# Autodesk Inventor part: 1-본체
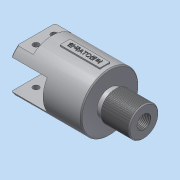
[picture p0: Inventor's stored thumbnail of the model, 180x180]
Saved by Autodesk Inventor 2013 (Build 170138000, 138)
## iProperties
Created: 2019-02
Part Number: 1-본체
Material: 알루미늄 6061
Document SubType Name: Modeling
Designer: Administrator
Density: 2.71 g/cm^3
Mass: 344.897 g
Surface Area: 291.439 cm^2
Volume: 127.268 cm^3
Author: Administrator
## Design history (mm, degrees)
sketch "스케치1"
  geometry: L1 (0, 0)-(72, 0); L2 (0, 14)-(0, 29); L3 (0, 29)-(38, 29); L4 (38, 29)-(38, 13); L5 (38, 13)-(43, 13); L6 (43, 13)-(43, 15); L7 (43, 15)-(72, 15); L8 (72, 15)-(72, 7); L9 (0, 14)-(2.65, 14); L10 (2.65, 14)-(2.65, 17); L11 (2.65, 17)-(7.35, 17); L12 (7.35, 17)-(7.35, 14); L13 (7.35, 14)-(11.65, 14); L14 (11.65, 14)-(11.65, 17); L15 (11.65, 17)-(16.35, 17); L16 (16.35, 17)-(16.35, 14); L17 (16.35, 14)-(20, 14); L18 (20, 14)-(20, 16); L19 (20, 16)-(27, 16); L20 (27, 16)-(27, 4); L21 (27, 4)-(47, 4); L22 (50, 7)-(72, 7); L23 (50, 7)-(47, 4); 2 further points
  constraints: 46 end point, 10 parallel, 7 perpendicular, 4 collinear, 2 horizontal, 2 midpoint, 1 vertical, 1 vertical alignment
  dimensions: "d0" = 58 diameter of L3 L1; "d1" = 38 distance of L2.end L3.end; "d2" = 5 distance of L4.end L5.end; "d3" = 29 distance of L6.end L7.end; "d4" = 26 diameter of L5 L1; "d5" = 30 diameter of L7 L1; "d6" = 7 distance of L18.end L19.end; "d7" = 9 distance of point (5, 17) point (14, 17); "d8" = 5 distance from line of L2 point (5, 17); "d9" = 4.7 distance between parallel lines of L12 L10; "d10" = 4.7 distance between parallel lines of L16 L14; "d11" = 34 diameter of point (5, 17) L1; "d12" = 28 diameter of L13 L1; "d13" = 32 diameter of L19 L1; "d14" = 27 distance between parallel lines of L2 L20; "d15" = 8 diameter of L21 L1; "d16" = 22 distance of L8.end L22.start; "d17" = 14 diameter of L22 L1; "d18" = 28 diameter of L9 L1; "d61" = 45 deg angle of L21 L23
revolve "회전1" sketch "스케치1" stored, may be unused: angle "d19" = 90 deg
feature "스레드1" dims "d20" = 18, "d21" = 0
feature "스레드2" dims "d22" = 10, "d23" = 0
sketch "스케치2"
  geometry: C1 r 29 at (0, 0) reference
extrude "돌출1" join sketch "스케치2" distance "d24" = 36; taper "d25" = 0 deg
sketch "스케치3"
  geometry: L1 (-15, 36.407)-(15, 36.407); L2 (15, 36.407)-(15, -36.407); L3 (15, -36.407)-(-15, -36.407); L4 (-15, -36.407)-(-15, 36.407); C1 r 29 at (0, 0) reference; 2 further points
  constraints: 8 end point, 2 midpoint, 2 parallel, 1 horizontal, 1 horizontal alignment, 1 perpendicular, 1 vertical alignment
  dimensions: "d26" = 30 distance of L1.start L1.end; "d27" = 72.81341 distance of L1.end L2.end
extrude "돌출2" cut sketch "스케치3" distance "d28" = 36; taper "d29" = 0 deg
sketch "스케치4"
  geometry: L1 (22, 43.311)-(53.385, 43.311); L2 (53.385, 43.311)-(53.385, -43.311); L3 (53.385, -43.311)-(22, -43.311); L4 (22, -43.311)-(22, 43.311); 2 further points
  constraints: 8 end point, 2 parallel, 1 horizontal, 1 horizontal alignment, 1 midpoint, 1 perpendicular
  dimensions: "d30" = 22 distance of point (22, 0) point (0, 0); "d31" = 31.38509 distance of L1.start L1.end; "d32" = 86.62286 distance of L1.end L2.end
extrude "돌출3" cut sketch "스케치4" distance "d33" = 16; taper "d34" = 0 deg
sketch "스케치5"
  geometry: L1 (16, 0)-(16, -37.789) reference; L2 (16, 5.925)-(16, -43.714) reference; C1 r 3 at (7, -9.894); C2 r 3 at (7, -27.894); 2 further points
  constraints: 2 centre point, 1 equal radius, 1 midpoint, 1 vertical alignment
  dimensions: "d35" = 9 distance from line of L1 C1.centre; "d36" = 18 distance of C1.centre C2.centre; "d37" = 9 horizontal distance of point (16, -18.894) C2.centre; "d38" = 6 diameter of C2
extrude "돌출4" cut sketch "스케치5" stored distance "d39" = 16; taper "d40" = 0 deg
node "작업 평면1"
sketch "스케치6"
  geometry: L1 (-7, 5)-(33, 5); L2 (33, 5)-(33, -5); L3 (33, -5)-(-7, -5); L4 (-7, -5)-(-7, 5); L5 (0, 24.819)-(0, -24.819) reference; L6 (38, -29)-(38, 29) reference; 3 further points
  constraints: 8 end point, 2 midpoint, 2 parallel, 1 horizontal, 1 horizontal alignment, 1 perpendicular
  dimensions: "d42" = 10 distance of L3.end L1.start; "d43" = 40 distance of L1.start L1.end; "d44" = 5 distance between parallel lines of L6 L2
extrude "돌출5" join sketch "스케치6" stored distance "d45" = 16; taper "d46" = 0 deg
sketch "스케치7"
  geometry: L1 (-7, -5)-(-7, 5) reference; L2 (33, -5)-(-7, -5) reference; 2 further points
  constraints: 1 other
  dimensions: "d47" = 20 distance from line of point (13, 0) L1; "d48" = 5 distance from line of L2 point (13, 0)
feature "엠보싱1" sketch "스케치7" dims "d49" = 0.5, "d50" = 0
chamfer "모따기1" distance "d51" = 1; stored, may be unused: second distance "d52" = 2, angle "d53" = 45 deg
fillet "모깎기1" dims "d57" = 0.8
chamfer "모따기4" distance "d62" = 1; stored, may be unused: second distance "d63" = 2, angle "d64" = 45 deg
node "솔리드1"
mirror "대칭1"
